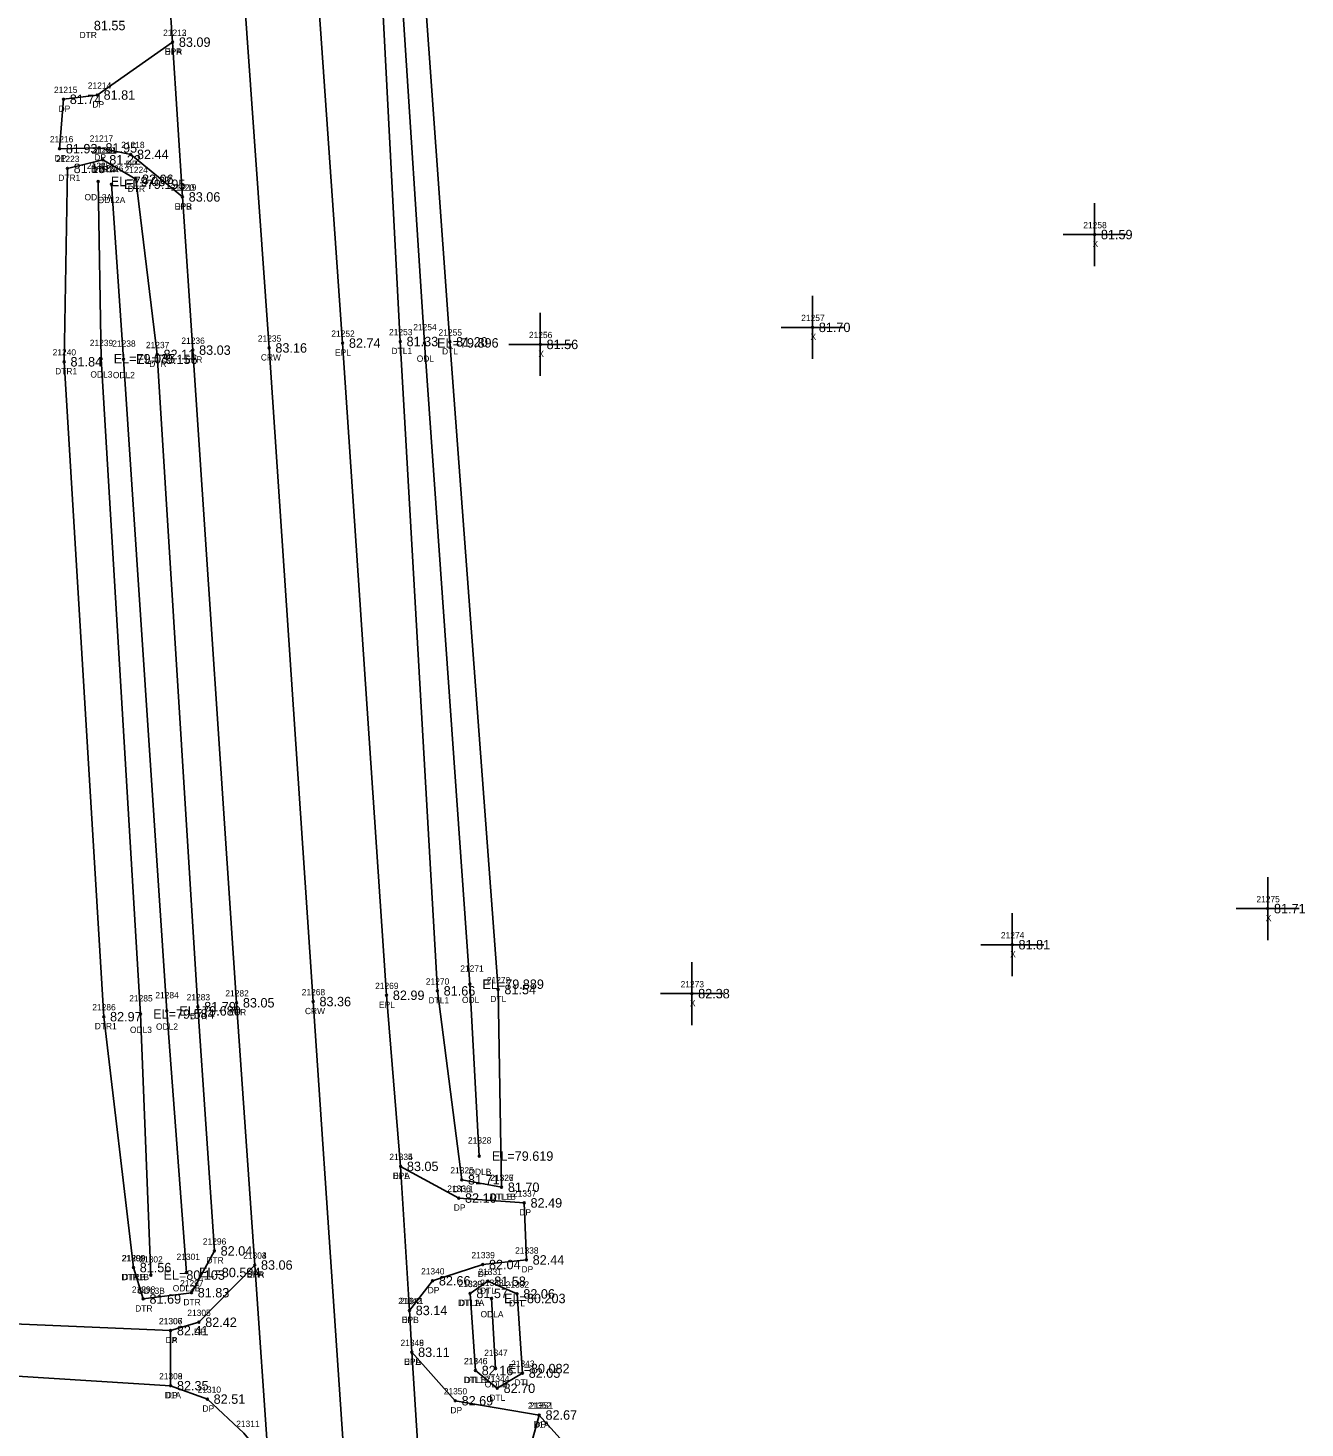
# Model space of a CAD drawing. Extents: x 2140110 to 2141565, y 506241 to 510327.
# Drawn here: x 2140554.8 to 2140757.7, y 507158.8 to 507381.3 of the extents above; entities that cross this region are included whole.
import ezdxf

# ---------------------------------------------------------------- set-up
doc = ezdxf.new("R2010")
doc.units = 0
for name, color, linetype in [('RD_DTM_BkLn1', 7, 'Continuous'), ('RD_EX_Driveway', 7, 'Continuous'), ('RD_EX_Driveway_txCode', 7, 'Continuous'), ('RD_EX_H2O', 7, 'Continuous'), ('RD_EX_H2O_txCode', 7, 'Continuous'), ('RD_EX_Misc', 7, 'Continuous'), ('RD_EX_Misc_txCode', 7, 'Continuous'), ('RD_EX_Road', 7, 'Continuous'), ('RD_EX_Road_txCode', 7, 'Continuous'), ('RD_EX_TX_Driveway_ELEV', 7, 'Continuous'), ('RD_EX_TX_H2O_ELEV', 7, 'Continuous'), ('RD_EX_TX_Misc_ELEV', 7, 'Continuous'), ('RD_EX_TX_Road_ELEV', 7, 'Continuous'), ('RD_HC_Survey_ELEV', 7, 'Continuous'), ('RD_HC_Survey_txCode', 7, 'Continuous'), ('RD_SMD_Locator', 7, 'Continuous')]:
    doc.layers.add(name, color=color, linetype=linetype)

msp = doc.modelspace()

# ---------------------------------------------------------------- linework, layer by layer
at = {"layer": 'RD_DTM_BkLn1'}
msp.add_lwpolyline([(2140572.08, 507731.46), (2140572.34, 507666.65), (2140574.39, 507611.67), (2140578.3, 507548.14), (2140582.03, 507493.09), (2140585.48, 507438.76), (2140593.15, 507330.44), (2140600.15, 507226.55), (2140607.03, 507125.06), (2140614.51, 507013.11), (2140621.67, 506908.37), (2140628.96, 506803.77), (2140636.45, 506691.52), (2140643.41, 506587.05), (2140651.3, 506473.51), (2140657.83, 506375.49), (2140665.56, 506264.07)], dxfattribs=at)
at = {"layer": 'RD_EX_Driveway'}
for points in [[(2140577.82, 507379.04), (2140565.86, 507370.64), (2140560.49, 507369.96), (2140559.86, 507362.11), (2140566.16, 507362.23), (2140571.16, 507361.2), (2140579.38, 507354.44)], [(2140614.04, 507200.36), (2140623.27, 507195.32), (2140633.68, 507194.55), (2140634.02, 507185.49), (2140627.08, 507184.75), (2140619.12, 507182.18), (2140615.44, 507177.46)], [(2140577.5, 507174.26), (2140494.03, 507177.83), (2140424.01, 507190.88)], [(2140590.86, 507184.68), (2140582, 507175.58), (2140577.5, 507174.26), (2140577.51, 507165.5), (2140583.34, 507163.37), (2140589.15, 507157.94), (2140593.07, 507153.16)], [(2140577.51, 507165.5), (2140491.76, 507170.87), (2140434.63, 507180.96)], [(2140615.82, 507170.81), (2140622.73, 507163.11), (2140636.06, 507160.84), (2140633.01, 507149.86), (2140622.39, 507149.81), (2140617.54, 507144.2)], [(2140636.06, 507160.84), (2140660.72, 507133.35), (2140676.06, 507123.7), (2140710.38, 507124.86)]]:
    msp.add_lwpolyline(points, dxfattribs=at)
at = {"layer": 'RD_EX_H2O'}
for p, q in [((2140625.07, 507180.17), (2140625.92, 507167.91)), ((2140628.48, 507179.36), (2140629.12, 507168.22))]:
    msp.add_line(p, q, dxfattribs=at)
for points in [[(2140603.99, 507551.21), (2140601.87, 507547.52), (2140605.21, 507495.06), (2140608.3, 507440.3), (2140613.99, 507331.46), (2140619.88, 507228.25), (2140623.74, 507198.23), (2140630.08, 507197.04)], [(2140603.99, 507551.21), (2140604.46, 507547.76), (2140607.73, 507495.4), (2140610.72, 507440.67), (2140617.84, 507331.24), (2140625.04, 507229.31), (2140626.54, 507201.99)], [(2140603.99, 507551.21), (2140608.04, 507548.03), (2140611.33, 507495.05), (2140614.04, 507440.89), (2140621.86, 507331.4), (2140629.53, 507228.46), (2140630.08, 507197.04)], [(2140566.76, 507360.34), (2140561.1, 507358.98), (2140560.6, 507328.24), (2140566.88, 507224.15), (2140571.6, 507184.27)], [(2140566.76, 507360.34), (2140571.96, 507357.24), (2140575.38, 507329.4), (2140581.84, 507225.74), (2140584.45, 507186.92), (2140580.81, 507180.28), (2140573.15, 507179.28), (2140571.6, 507184.27)], [(2140566.01, 507356.9), (2140566.46, 507328.73), (2140572.73, 507224.57), (2140574.37, 507183.08)], [(2140568.1, 507356.45), (2140570.02, 507328.63), (2140576.88, 507225.07), (2140580.01, 507183.49)], [(2140625.07, 507180.17), (2140627.92, 507182.1), (2140632.53, 507180.09), (2140633.39, 507167.5), (2140629.4, 507165.09), (2140625.92, 507167.91)]]:
    msp.add_lwpolyline(points, dxfattribs=at)
at = {"layer": 'RD_EX_Misc'}
for p, q in [((2140724.29, 507343.46), (2140724.29, 507353.46)), ((2140719.29, 507348.46), (2140729.29, 507348.46)), ((2140679.48, 507328.71), (2140679.48, 507338.71)), ((2140636.23, 507326), (2140636.23, 507336)), ((2140674.48, 507333.71), (2140684.48, 507333.71)), ((2140631.23, 507331), (2140641.23, 507331)), ((2140751.78, 507236.33), (2140751.78, 507246.33)), ((2140711.2, 507230.59), (2140711.2, 507240.59)), ((2140746.78, 507241.33), (2140756.78, 507241.33)), ((2140706.2, 507235.59), (2140716.2, 507235.59)), ((2140660.31, 507222.81), (2140660.31, 507232.81)), ((2140655.31, 507227.81), (2140665.31, 507227.81))]:
    msp.add_line(p, q, dxfattribs=at)
at = {"layer": 'RD_EX_Road'}
for points in [[(2140583.43, 507730.59), (2140583.94, 507673.5), (2140583.85, 507666.58), (2140586.13, 507612.82), (2140586.39, 507606.18), (2140590.25, 507541.6), (2140593.48, 507494.33), (2140597.22, 507439.46), (2140604.83, 507331.21), (2140611.81, 507227.55), (2140614.04, 507200.36), (2140615.44, 507177.46), (2140615.82, 507170.81), (2140617.54, 507144.2)], [(2140559.74, 507699.59), (2140559.81, 507681.93), (2140560.3, 507666.18), (2140562.28, 507610.8), (2140566.4, 507547.54), (2140570.03, 507492.8), (2140573.82, 507437.38), (2140577.82, 507379.04), (2140579.38, 507354.44), (2140581.03, 507330.09), (2140587.99, 507226.36), (2140590.86, 507184.68), (2140593.07, 507153.16), (2140595.23, 507123.79), (2140602.7, 507012.79), (2140610.01, 506906.42), (2140617.09, 506803.24), (2140624.73, 506690.17), (2140631.76, 506586.09), (2140639.51, 506472.79), (2140646.1, 506374.38), (2140653.64, 506264.11)]]:
    msp.add_lwpolyline(points, dxfattribs=at)
at = {"layer": 'RD_SMD_Locator'}
for centre in [(2140577.82, 507379.04), (2140577.82, 507379.04), (2140560.49, 507369.96), (2140565.86, 507370.64), (2140559.86, 507362.11), (2140566.16, 507362.23), (2140571.16, 507361.2), (2140561.1, 507358.98), (2140566.76, 507360.34), (2140566.76, 507360.34), (2140566.01, 507356.9), (2140568.1, 507356.45), (2140571.96, 507357.24), (2140579.38, 507354.44), (2140579.38, 507354.44), (2140724.29, 507348.46), (2140679.48, 507333.71), (2140575.38, 507329.4), (2140581.03, 507330.09), (2140593.15, 507330.44), (2140604.83, 507331.21), (2140613.99, 507331.46), (2140617.84, 507331.24), (2140621.86, 507331.4), (2140636.23, 507331), (2140560.6, 507328.24), (2140566.46, 507328.73), (2140570.02, 507328.63), (2140751.78, 507241.33), (2140711.2, 507235.59), (2140625.04, 507229.31), (2140611.81, 507227.55), (2140619.88, 507228.25), (2140629.53, 507228.46), (2140660.31, 507227.81), (2140576.88, 507225.07), (2140581.84, 507225.74), (2140587.99, 507226.36), (2140600.15, 507226.55), (2140566.88, 507224.15), (2140572.73, 507224.57), (2140614.04, 507200.36), (2140614.04, 507200.36), (2140626.54, 507201.99), (2140623.74, 507198.23), (2140630.08, 507197.04), (2140630.08, 507197.04), (2140623.27, 507195.32), (2140633.68, 507194.55), (2140584.45, 507186.92), (2140627.08, 507184.75), (2140634.02, 507185.49), (2140571.6, 507184.27), (2140571.6, 507184.27), (2140574.37, 507183.08), (2140580.01, 507183.49), (2140590.86, 507184.68), (2140590.86, 507184.68), (2140580.81, 507180.28), (2140619.12, 507182.18), (2140627.92, 507182.1), (2140573.15, 507179.28), (2140625.07, 507180.17), (2140625.07, 507180.17), (2140628.48, 507179.36), (2140632.53, 507180.09), (2140615.44, 507177.46), (2140615.44, 507177.46), (2140577.5, 507174.26), (2140577.5, 507174.26), (2140582, 507175.58), (2140615.82, 507170.81), (2140615.82, 507170.81), (2140625.92, 507167.91), (2140625.92, 507167.91), (2140629.12, 507168.22), (2140633.39, 507167.5), (2140577.51, 507165.5), (2140577.51, 507165.5), (2140629.4, 507165.09), (2140583.34, 507163.37), (2140622.73, 507163.11), (2140636.06, 507160.84), (2140636.06, 507160.84)]:
    msp.add_circle(centre, 0.15, dxfattribs=at)

# ---------------------------------------------------------------- texts
at = {"layer": 'RD_EX_Driveway_txCode'}
for s, p in [('21213', (2140576.31, 507380.04)), ('DPA', (2140576.55, 507377.04)), ('21215', (2140558.98, 507370.96)), ('21214', (2140564.35, 507371.64)), ('DP', (2140565.08, 507368.64)), ('DP', (2140559.71, 507367.96)), ('21216', (2140558.33, 507363.11)), ('21217', (2140564.65, 507363.23)), ('21218', (2140569.65, 507362.2)), ('DP', (2140559.08, 507360.11)), ('DP', (2140565.38, 507360.23)), ('DP', (2140570.38, 507359.2)), ('21219', (2140577.87, 507355.44)), ('DPB', (2140578.13, 507352.44)), ('21335', (2140612.25, 507201.36)), ('DPA', (2140612.77, 507198.36)), ('21336', (2140621.45, 507196.32)), ('21337', (2140631.89, 507195.55)), ('DP', (2140622.49, 507193.32)), ('DP', (2140632.9, 507192.55)), ('21338', (2140632.23, 507186.49)), ('21304', (2140589.03, 507185.68)), ('21339', (2140625.29, 507185.75)), ('DPA', (2140589.59, 507182.68)), ('21340', (2140617.29, 507183.18)), ('DP', (2140626.3, 507182.75)), ('DP', (2140633.24, 507183.49)), ('DP', (2140618.34, 507180.18)), ('21341', (2140613.93, 507178.46)), ('21306', (2140575.64, 507175.26)), ('21307', (2140575.67, 507175.26)), ('21305', (2140580.16, 507176.58)), ('DPB', (2140614.19, 507175.46)), ('DP', (2140581.22, 507173.58)), ('DA', (2140576.7, 507172.26)), ('DP', (2140576.72, 507172.26)), ('21349', (2140614.02, 507171.81)), ('DPA', (2140614.55, 507168.81)), ('21308', (2140575.67, 507166.5)), ('21309', (2140575.67, 507166.5)), ('21310', (2140581.79, 507164.37)), ('21350', (2140620.89, 507164.11)), ('D1A', (2140576.55, 507163.5)), ('DP', (2140576.73, 507163.5)), ('21352', (2140634.26, 507161.84)), ('21351', (2140634.54, 507161.84)), ('DP', (2140582.56, 507161.37)), ('DP', (2140621.95, 507161.11)), ('21311', (2140587.92, 507158.94)), ('D1A', (2140635.1, 507158.84)), ('DP', (2140635.28, 507158.84))]:
    msp.add_text(s, height=1, dxfattribs=at).set_placement(p)
at = {"layer": 'RD_EX_H2O_txCode'}
for s, p in [('DTR', (2140563.04, 507379.68)), ('21223', (2140559.3, 507359.98)), ('21222', (2140564.96, 507361.34)), ('21221', (2140565.24, 507361.34)), ('21225', (2140564.21, 507358.9)), ('DTR1A', (2140564.84, 507358.34)), ('DTRA', (2140565, 507358.34)), ('21226', (2140566.28, 507358.45)), ('21224', (2140570.17, 507358.24)), ('DTR1', (2140559.66, 507356.98)), ('DTR', (2140570.7, 507355.24)), ('ODL3A', (2140563.83, 507353.9)), ('ODL2A', (2140565.92, 507353.45)), ('21254', (2140616.05, 507333.24)), ('21239', (2140564.66, 507330.73)), ('21253', (2140612.2, 507332.46)), ('21255', (2140620.07, 507332.4)), ('21240', (2140558.76, 507329.24)), ('21238', (2140568.23, 507330.63)), ('21237', (2140573.58, 507330.4)), ('DTL1', (2140612.59, 507329.46)), ('DTL', (2140620.62, 507329.4)), ('DTR1', (2140559.16, 507326.24)), ('DTR', (2140574.11, 507327.4)), ('ODL', (2140616.6, 507328.24)), ('ODL3', (2140564.76, 507325.73)), ('ODL2', (2140568.33, 507325.63)), ('21271', (2140623.52, 507231.31)), ('21270', (2140618.05, 507229.25)), ('21272', (2140627.74, 507229.46)), ('21285', (2140570.93, 507226.57)), ('21284', (2140575.08, 507227.07)), ('21283', (2140580.05, 507226.74)), ('DTL1', (2140618.47, 507226.25)), ('ODL', (2140623.79, 507226.31)), ('DTL', (2140628.29, 507226.46)), ('21286', (2140565.06, 507225.15)), ('DTR1', (2140565.45, 507222.15)), ('ODL2', (2140575.18, 507222.07)), ('DTR', (2140580.58, 507223.74)), ('ODL3', (2140571.04, 507221.57)), ('21328', (2140624.74, 507203.99)), ('21325', (2140621.94, 507199.23)), ('ODLB', (2140624.82, 507198.99)), ('21326', (2140628.26, 507198.04)), ('21327', (2140628.28, 507198.04)), ('DTL1', (2140622.33, 507196.23)), ('DTL1B', (2140628.19, 507195.04)), ('DTLB', (2140628.36, 507195.04)), ('21296', (2140582.63, 507187.92)), ('21300', (2140569.72, 507185.27)), ('21299', (2140569.8, 507185.27)), ('21302', (2140572.53, 507185.08)), ('21301', (2140578.45, 507185.49)), ('DTR', (2140583.18, 507184.92)), ('DTR1B', (2140569.69, 507182.27)), ('DTRB', (2140569.86, 507182.27)), ('21331', (2140626.4, 507183.1)), ('21298', (2140571.35, 507180.28)), ('ODL3B', (2140572.2, 507180.08)), ('ODL2B', (2140577.84, 507180.49)), ('21297', (2140579.01, 507181.28)), ('21330', (2140623.23, 507181.17)), ('21329', (2140623.27, 507181.17)), ('21333', (2140626.68, 507181.36)), ('DTL', (2140626.67, 507180.1)), ('21332', (2140630.73, 507181.09)), ('DTR', (2140571.88, 507177.28)), ('DTR', (2140579.54, 507178.28)), ('DTL1A', (2140623.17, 507178.17)), ('DTLA', (2140623.34, 507178.17)), ('DTL', (2140631.28, 507178.09)), ('ODLA', (2140626.74, 507176.36)), ('21346', (2140624.1, 507168.91)), ('21345', (2140624.13, 507168.91)), ('21347', (2140627.32, 507170.22)), ('21343', (2140631.59, 507168.5)), ('21344', (2140627.6, 507166.09)), ('DTL1B', (2140624.04, 507165.91)), ('DTLB', (2140624.21, 507165.91)), ('ODLB', (2140627.4, 507165.22)), ('DTL', (2140632.14, 507165.5)), ('DTL', (2140628.15, 507163.09))]:
    msp.add_text(s, height=1, dxfattribs=at).set_placement(p)
at = {"layer": 'RD_EX_Misc_txCode'}
for s, p in [('21258', (2140722.49, 507349.46)), ('X', (2140723.97, 507346.46)), ('21257', (2140677.68, 507334.71)), ('21256', (2140634.42, 507332)), ('X', (2140679.16, 507331.71)), ('X', (2140635.92, 507329)), ('21275', (2140749.99, 507242.33)), ('X', (2140751.47, 507239.33)), ('21274', (2140709.4, 507236.59)), ('X', (2140710.88, 507233.59)), ('21273', (2140658.52, 507228.81)), ('X', (2140660, 507225.81))]:
    msp.add_text(s, height=1, dxfattribs=at).set_placement(p)
at = {"layer": 'RD_EX_Road_txCode'}
for s, p in [('21212', (2140576.31, 507380.04)), ('EPR', (2140576.59, 507377.04)), ('21220', (2140577.54, 507355.44)), ('EPR', (2140578.15, 507352.44)), ('21236', (2140579.21, 507331.09)), ('21252', (2140603.03, 507332.21)), ('EPL', (2140603.62, 507329.21)), ('EPR', (2140579.8, 507328.09)), ('21269', (2140609.99, 507228.55)), ('21282', (2140586.2, 507227.36)), ('EPR', (2140586.76, 507224.36)), ('EPL', (2140610.6, 507225.55)), ('21334', (2140612.25, 507201.36)), ('EPL', (2140612.84, 507198.36)), ('21303', (2140589.03, 507185.68)), ('EPR', (2140589.63, 507182.68)), ('21342', (2140613.64, 507178.46)), ('EPL', (2140614.23, 507175.46)), ('21348', (2140614.02, 507171.81)), ('EPL', (2140614.61, 507168.81))]:
    msp.add_text(s, height=1, dxfattribs=at).set_placement(p)
at = {"layer": 'RD_EX_TX_Driveway_ELEV'}
for s, p in [('83.09', (2140578.82, 507378.29)), ('81.74', (2140561.49, 507369.21)), ('81.81', (2140566.86, 507369.89)), ('81.93', (2140560.86, 507361.36)), ('81.95', (2140567.16, 507361.48)), ('82.44', (2140572.16, 507360.45)), ('83.06', (2140580.38, 507353.69)), ('83.05', (2140615.04, 507199.61)), ('82.10', (2140624.27, 507194.57)), ('82.49', (2140634.68, 507193.8)), ('83.06', (2140591.86, 507183.93)), ('82.04', (2140628.08, 507184)), ('82.44', (2140635.02, 507184.74)), ('82.66', (2140620.12, 507181.43)), ('83.14', (2140616.44, 507176.71)), ('82.42', (2140583, 507174.83)), ('82.41', (2140578.5, 507173.51)), ('82.41', (2140578.5, 507173.51)), ('83.11', (2140616.82, 507170.06)), ('82.35', (2140578.51, 507164.75)), ('82.35', (2140578.51, 507164.75)), ('82.51', (2140584.34, 507162.62)), ('82.69', (2140623.73, 507162.36)), ('82.67', (2140637.06, 507160.09)), ('82.67', (2140637.06, 507160.09))]:
    msp.add_text(s, height=1.5, dxfattribs=at).set_placement(p)
at = {"layer": 'RD_EX_TX_H2O_ELEV'}
for s, p in [('81.55', (2140565.31, 507380.93)), ('81.22', (2140567.76, 507359.59)), ('81.22', (2140567.76, 507359.59)), ('81.15', (2140562.1, 507358.23)), ('EL=79.037', (2140568.01, 507356.15)), ('EL=79.195', (2140570.1, 507355.7)), ('82.06', (2140572.96, 507356.49)), ('81.33', (2140614.99, 507330.71)), ('EL=79.896', (2140619.84, 507330.49)), ('81.20', (2140622.86, 507330.65)), ('EL=79.035', (2140568.46, 507327.98)), ('82.11', (2140576.38, 507328.65)), ('81.84', (2140561.6, 507327.49)), ('EL=79.156', (2140572.02, 507327.88)), ('EL=79.889', (2140627.04, 507228.56)), ('81.66', (2140620.88, 507227.5)), ('81.54', (2140630.53, 507227.71)), ('82.97', (2140567.88, 507223.4)), ('EL=79.584', (2140574.73, 507223.82)), ('EL=79.680', (2140578.88, 507224.32)), ('81.79', (2140582.84, 507224.99)), ('EL=79.619', (2140628.54, 507201.24)), ('81.71', (2140624.74, 507197.48)), ('81.70', (2140631.08, 507196.29)), ('81.70', (2140631.08, 507196.29)), ('82.04', (2140585.45, 507186.17)), ('81.56', (2140572.6, 507183.52)), ('81.56', (2140572.6, 507183.52)), ('EL=80.103', (2140576.37, 507182.33)), ('EL=80.594', (2140582.01, 507182.74)), ('81.58', (2140628.92, 507181.35)), ('81.83', (2140581.81, 507179.53)), ('81.57', (2140626.07, 507179.42)), ('81.57', (2140626.07, 507179.42)), ('82.06', (2140633.53, 507179.34)), ('81.69', (2140574.15, 507178.53)), ('EL=80.203', (2140630.48, 507178.61)), ('82.16', (2140626.92, 507167.16)), ('82.16', (2140626.92, 507167.16)), ('EL=80.082', (2140631.12, 507167.47)), ('82.05', (2140634.39, 507166.75)), ('82.70', (2140630.4, 507164.34))]:
    msp.add_text(s, height=1.5, dxfattribs=at).set_placement(p)
at = {"layer": 'RD_EX_TX_Misc_ELEV'}
for s, p in [('81.59', (2140725.29, 507347.71)), ('81.70', (2140680.48, 507332.96)), ('81.56', (2140637.23, 507330.25)), ('81.71', (2140752.78, 507240.58)), ('81.81', (2140712.2, 507234.84)), ('82.38', (2140661.31, 507227.06))]:
    msp.add_text(s, height=1.5, dxfattribs=at).set_placement(p)
at = {"layer": 'RD_EX_TX_Road_ELEV'}
for s, p in [('83.09', (2140578.82, 507378.29)), ('83.06', (2140580.38, 507353.69)), ('82.74', (2140605.83, 507330.46)), ('83.03', (2140582.03, 507329.34)), ('83.05', (2140588.99, 507225.61)), ('82.99', (2140612.81, 507226.8)), ('83.05', (2140615.04, 507199.61)), ('83.06', (2140591.86, 507183.93)), ('83.14', (2140616.44, 507176.71)), ('83.11', (2140616.82, 507170.06))]:
    msp.add_text(s, height=1.5, dxfattribs=at).set_placement(p)
at = {"layer": 'RD_HC_Survey_ELEV'}
for s, p in [('83.16', (2140594.15, 507329.69)), ('83.36', (2140601.15, 507225.8))]:
    msp.add_text(s, height=1.5, dxfattribs=at).set_placement(p)
at = {"layer": 'RD_HC_Survey_txCode'}
for s, p in [('21235', (2140591.36, 507331.44)), ('CRW', (2140591.84, 507328.44)), ('21268', (2140598.33, 507227.55)), ('CRW', (2140598.84, 507224.55))]:
    msp.add_text(s, height=1, dxfattribs=at).set_placement(p)

doc.saveas('drawing.dxf')
